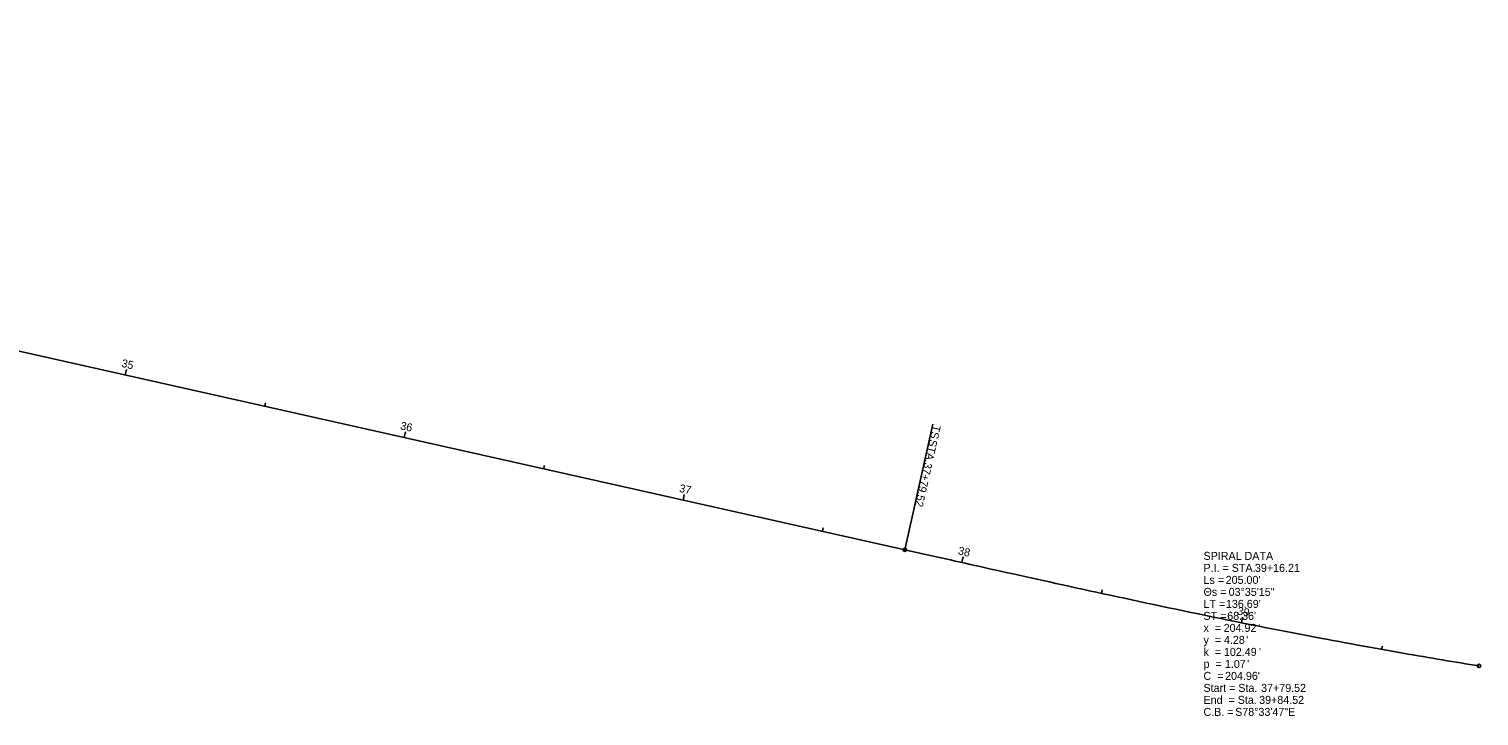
# Model space of a CAD drawing. Extents: x 198556 to 202876, y 391595 to 392065.
# Drawn here: x 199063 to 199570, y 391687 to 391928 of the extents above; entities that cross this region are included whole.
import ezdxf

# ---------------------------------------------------------------- set-up
doc = ezdxf.new("R2010")
doc.units = 0
for name, color, linetype in [('GE_X_Alignment', 7, 'Continuous'), ('GE_X_Alignment_100_Cardinal_Points', 7, 'Continuous'), ('GE_X_Alignment_100_Curve_Data', 7, 'Continuous'), ('GE_X_Alignment_100_Stations', 7, 'Continuous'), ('SC_Scratch3', 7, 'Continuous')]:
    doc.layers.add(name, color=color, linetype=linetype)

msp = doc.modelspace()

# ---------------------------------------------------------------- linework, layer by layer
at = {"layer": 'GE_X_Alignment'}
msp.add_line((198556.31, 391927.88), (199369.45, 391745.64), dxfattribs=at)
msp.add_open_spline([(199369.45, 391745.64), (199377.78, 391743.77), (199394.45, 391740.03), (199427.81, 391732.63), (199469.55, 391723.61), (199511.44, 391715.25), (199545.06, 391709.16), (199561.91, 391706.34), (199570.34, 391705)], degree=3, dxfattribs=at)
at = {"layer": 'GE_X_Alignment_100_Cardinal_Points'}
msp.add_line((199369.45, 391745.64), (199379.29, 391789.55), dxfattribs=at)
for centre in [(199369.45, 391745.64), (199570.34, 391705)]:
    msp.add_circle(centre, 0.6, dxfattribs=at)
at = {"layer": 'GE_X_Alignment_100_Stations'}
for p, q in [((199096.7, 391806.77), (199097.13, 391808.72)), ((199145.49, 391795.83), (199145.75, 391797.01)), ((199194.27, 391784.9), (199194.71, 391786.85)), ((199243.06, 391773.96), (199243.33, 391775.14)), ((199291.85, 391763.03), (199292.29, 391764.98)), ((199340.64, 391752.09), (199340.91, 391753.27)), ((199389.43, 391741.16), (199389.87, 391743.12)), ((199438.26, 391730.39), (199438.51, 391731.57)), ((199487.2, 391720.14), (199487.59, 391722.1)), ((199536.31, 391710.76), (199536.52, 391711.94))]:
    msp.add_line(p, q, dxfattribs=at)
at = {"layer": 'SC_Scratch3'}
msp.add_open_spline([(199369.45, 391745.64), (199377.78, 391743.77), (199394.45, 391740.03), (199427.81, 391732.63), (199469.55, 391723.61), (199511.44, 391715.25), (199545.06, 391709.16), (199561.91, 391706.34), (199570.34, 391705)], degree=3, dxfattribs=at)

# ---------------------------------------------------------------- texts
at = {"layer": 'GE_X_Alignment_100_Cardinal_Points'}
for s, p in [(' STA. ', (199378.41, 391785.45)), ('TS', (199379.31, 391789.46)), ('37+79.52', (199376.37, 391776.35))]:
    msp.add_text(s, height=2.8, rotation=257.3672, dxfattribs=at).set_placement(p)
at = {"layer": 'GE_X_Alignment_100_Curve_Data'}
for s, p in [('SPIRAL DATA', (199473.96, 391742.1)), ('P.I. = STA. ', (199473.96, 391737.9)), ('39+16.21', (199491.95, 391737.9)), ('Ls = ', (199473.96, 391733.7)), ("205.00'", (199481.71, 391733.7)), ('Θs = ', (199473.96, 391729.5)), ('03°35\'15"', (199482.75, 391729.5)), ('ST = ', (199473.96, 391721.1)), ('LT = ', (199473.96, 391725.3)), ("136.69'", (199481.81, 391725.3)), ("68.36'", (199482.26, 391721.1)), ('x  = ', (199473.96, 391716.9)), ('204.92', (199481, 391716.9)), ("'", (199493.25, 391716.9)), ('y  = ', (199473.96, 391712.7)), ('4.28', (199481.1, 391712.7)), ("'", (199488.88, 391712.7)), ('k  = ', (199473.96, 391708.5)), ('102.49', (199481.1, 391708.5)), ("'", (199493.35, 391708.5)), ('C  = ', (199473.96, 391700.1)), ('p  = ', (199473.96, 391704.3)), ("204.96'", (199481.51, 391700.1)), ('1.07', (199481.44, 391704.3)), ("'", (199489.22, 391704.3)), ('Start = Sta. ', (199473.96, 391695.9)), ('37+79.52', (199494.11, 391695.9)), ('End  = Sta. ', (199473.96, 391691.7)), ('39+84.52', (199493.42, 391691.7)), ('C.B. = ', (199473.96, 391687.5)), ('S78°33\'47"E', (199485.03, 391687.5))]:
    msp.add_text(s, height=2.8, dxfattribs=at).set_placement(p)
at = {"layer": 'GE_X_Alignment_100_Stations'}
for s, rotation, p in [('35', 347.3672, (199095.2, 391809.67)), ('36', 347.3672, (199192.74, 391787.81)), ('37', 347.3672, (199290.33, 391765.93)), ('38', 347.403, (199387.9, 391744.07)), ('39', 348.6063, (199485.62, 391723.01))]:
    msp.add_text(s, height=2.8, rotation=rotation, dxfattribs=at).set_placement(p)

doc.saveas('drawing.dxf')
